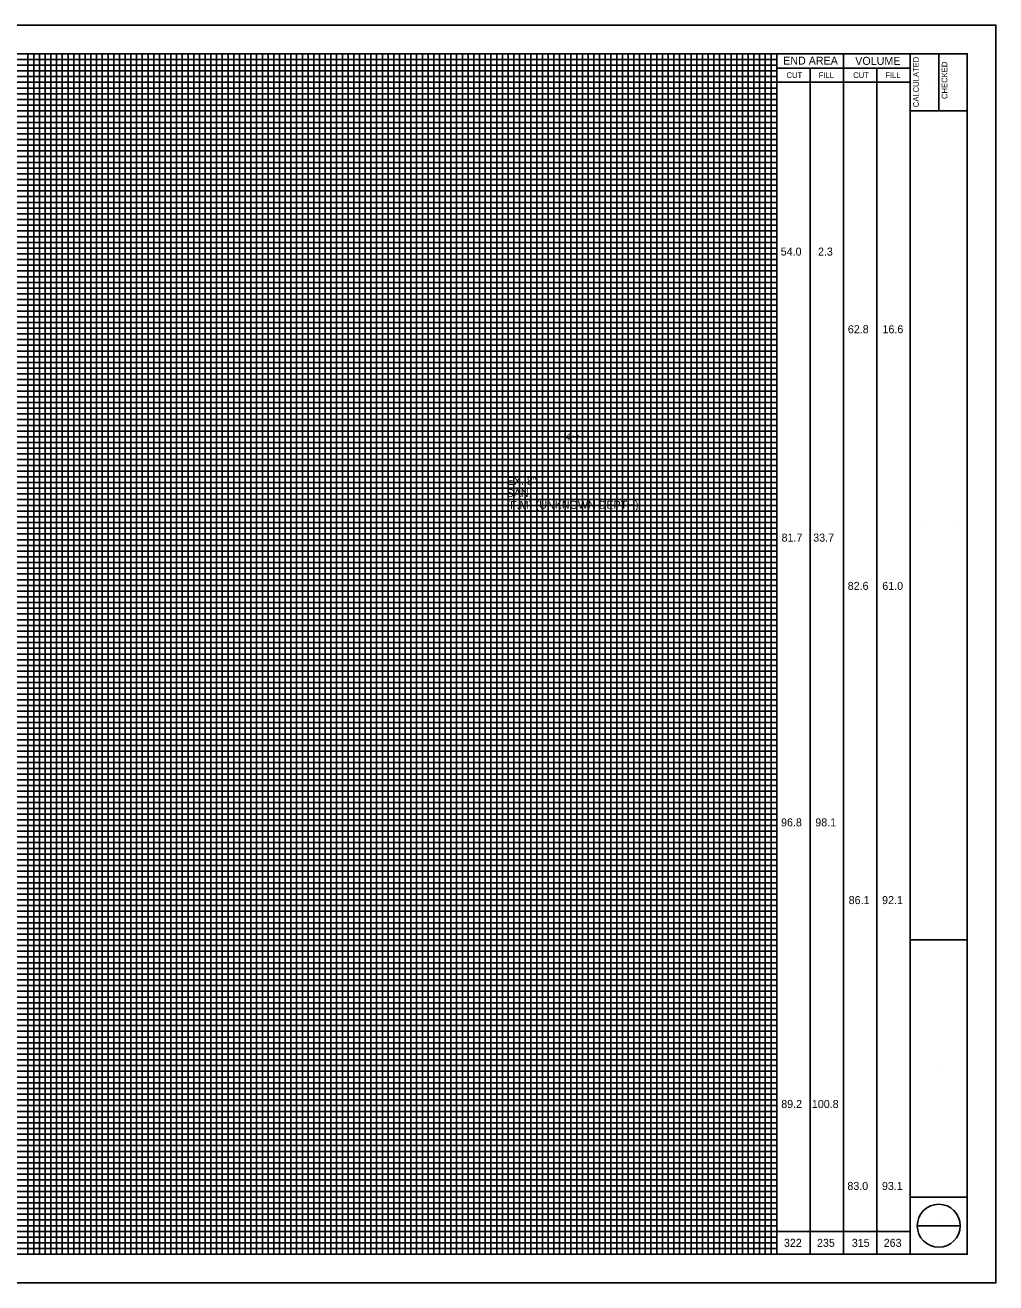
# Model space of a CAD drawing. Extents: x 2267521 to 2268201, y 654563 to 655003.
# Drawn here: x 2267861.3 to 2268201, y 654563.4 to 655003.4 of the extents above; entities that cross this region are included whole.
import ezdxf

# ---------------------------------------------------------------- set-up
doc = ezdxf.new("R2010")
doc.units = 0
for name, color, linetype in [('CL_X_Construction', 7, 'Continuous'), ('GK_Cells', 7, 'Continuous'), ('GK_Patterns', 7, 'Continuous'), ('MD_P_Surface_Finished_Grade', 7, 'Continuous'), ('PF_X_Ground_Line', 7, 'Continuous'), ('XS_X_Ground_Line', 7, 'Continuous')]:
    doc.layers.add(name, color=color, linetype=linetype)

msp = doc.modelspace()

# ---------------------------------------------------------------- linework, layer by layer
at = {"layer": 'CL_X_Construction'}
msp.add_lwpolyline([(2267520.96, 654563.36), (2268200.96, 654563.36), (2268200.96, 655003.36), (2267520.96, 655003.36)], close=True, dxfattribs=at)
at = {"layer": 'GK_Cells'}
for p, q in [((2267862.29, 654573.36), (2267862.29, 654993.36)), ((2267866.29, 654573.36), (2267866.29, 654993.36)), ((2267868.29, 654573.36), (2267868.29, 654993.36)), ((2267870.29, 654573.36), (2267870.29, 654993.36)), ((2267872.29, 654573.36), (2267872.29, 654993.36)), ((2267874.29, 654573.36), (2267874.29, 654993.36)), ((2267876.29, 654573.36), (2267876.29, 654993.36)), ((2267878.29, 654573.36), (2267878.29, 654993.36)), ((2267880.29, 654573.36), (2267880.29, 654993.36)), ((2267882.29, 654573.36), (2267882.29, 654993.36)), ((2267886.29, 654573.36), (2267886.29, 654993.36)), ((2267888.29, 654573.36), (2267888.29, 654993.36)), ((2267890.29, 654573.36), (2267890.29, 654993.36)), ((2267892.29, 654573.36), (2267892.29, 654993.36)), ((2267894.29, 654573.36), (2267894.29, 654993.36)), ((2267896.29, 654573.36), (2267896.29, 654993.36)), ((2267898.29, 654573.36), (2267898.29, 654993.36)), ((2267900.29, 654573.36), (2267900.29, 654993.36)), ((2267902.29, 654573.36), (2267902.29, 654993.36)), ((2267906.29, 654573.36), (2267906.29, 654993.36)), ((2267908.29, 654573.36), (2267908.29, 654993.36)), ((2267910.29, 654573.36), (2267910.29, 654993.36)), ((2267912.29, 654573.36), (2267912.29, 654993.36)), ((2267914.29, 654573.36), (2267914.29, 654993.36)), ((2267916.29, 654573.36), (2267916.29, 654993.36)), ((2267918.29, 654573.36), (2267918.29, 654993.36)), ((2267920.29, 654573.36), (2267920.29, 654993.36)), ((2267922.29, 654573.36), (2267922.29, 654993.36)), ((2267926.29, 654573.36), (2267926.29, 654993.36)), ((2267928.29, 654573.36), (2267928.29, 654993.36)), ((2267930.29, 654573.36), (2267930.29, 654993.36)), ((2267932.29, 654573.36), (2267932.29, 654993.36)), ((2267934.29, 654573.36), (2267934.29, 654993.36)), ((2267936.29, 654573.36), (2267936.29, 654993.36)), ((2267938.29, 654573.36), (2267938.29, 654993.36)), ((2267940.29, 654573.36), (2267940.29, 654993.36)), ((2267942.29, 654573.36), (2267942.29, 654993.36)), ((2267946.29, 654573.36), (2267946.29, 654993.36)), ((2267948.29, 654573.36), (2267948.29, 654993.36)), ((2267950.29, 654573.36), (2267950.29, 654993.36)), ((2267952.29, 654573.36), (2267952.29, 654993.36)), ((2267954.29, 654573.36), (2267954.29, 654993.36)), ((2267956.29, 654573.36), (2267956.29, 654993.36)), ((2267958.29, 654573.36), (2267958.29, 654993.36)), ((2267960.29, 654573.36), (2267960.29, 654993.36)), ((2267962.29, 654573.36), (2267962.29, 654993.36)), ((2267966.29, 654573.36), (2267966.29, 654993.36)), ((2267968.29, 654573.36), (2267968.29, 654993.36)), ((2267970.29, 654573.36), (2267970.29, 654993.36)), ((2267972.29, 654573.36), (2267972.29, 654993.36)), ((2267974.29, 654573.36), (2267974.29, 654993.36)), ((2267976.29, 654573.36), (2267976.29, 654993.36)), ((2267978.29, 654573.36), (2267978.29, 654993.36)), ((2267980.29, 654573.36), (2267980.29, 654993.36)), ((2267982.29, 654573.36), (2267982.29, 654993.36)), ((2267986.29, 654573.36), (2267986.29, 654993.36)), ((2267988.29, 654573.36), (2267988.29, 654993.36)), ((2267990.29, 654573.36), (2267990.29, 654993.36)), ((2267992.29, 654573.36), (2267992.29, 654993.36)), ((2267994.29, 654573.36), (2267994.29, 654993.36)), ((2267996.29, 654573.36), (2267996.29, 654993.36)), ((2267998.29, 654573.36), (2267998.29, 654993.36)), ((2268000.29, 654573.36), (2268000.29, 654993.36)), ((2268002.29, 654573.36), (2268002.29, 654993.36)), ((2268006.29, 654573.36), (2268006.29, 654993.36)), ((2268008.29, 654573.36), (2268008.29, 654993.36)), ((2268010.29, 654573.36), (2268010.29, 654993.36)), ((2268012.29, 654573.36), (2268012.29, 654993.36)), ((2268014.29, 654573.36), (2268014.29, 654993.36)), ((2268016.29, 654573.36), (2268016.29, 654993.36)), ((2268018.29, 654573.36), (2268018.29, 654993.36)), ((2268020.29, 654573.36), (2268020.29, 654993.36)), ((2268022.29, 654573.36), (2268022.29, 654993.36)), ((2268026.29, 654573.36), (2268026.29, 654993.36)), ((2268028.29, 654573.36), (2268028.29, 654993.36)), ((2268030.29, 654573.36), (2268030.29, 654993.36)), ((2268032.29, 654573.36), (2268032.29, 654993.36)), ((2268034.29, 654573.36), (2268034.29, 654993.36)), ((2268036.29, 654573.36), (2268036.29, 654993.36)), ((2268038.29, 654573.36), (2268038.29, 654993.36)), ((2268040.29, 654573.36), (2268040.29, 654993.36)), ((2268042.29, 654573.36), (2268042.29, 654993.36)), ((2268046.29, 654573.36), (2268046.29, 654993.36)), ((2268048.29, 654573.36), (2268048.29, 654993.36)), ((2268050.29, 654573.36), (2268050.29, 654993.36)), ((2268052.29, 654573.36), (2268052.29, 654993.36)), ((2268054.29, 654573.36), (2268054.29, 654993.36)), ((2268056.29, 654573.36), (2268056.29, 654993.36)), ((2268058.29, 654573.36), (2268058.29, 654993.36)), ((2268060.29, 654573.36), (2268060.29, 654993.36)), ((2268062.29, 654573.36), (2268062.29, 654993.36)), ((2268066.29, 654573.36), (2268066.29, 654993.36)), ((2268068.29, 654573.36), (2268068.29, 654993.36)), ((2268070.29, 654573.36), (2268070.29, 654993.36)), ((2268072.29, 654573.36), (2268072.29, 654993.36)), ((2268074.29, 654573.36), (2268074.29, 654993.36)), ((2268076.29, 654573.36), (2268076.29, 654993.36)), ((2268078.29, 654573.36), (2268078.29, 654993.36)), ((2268080.29, 654573.36), (2268080.29, 654993.36)), ((2268082.29, 654573.36), (2268082.29, 654993.36)), ((2268086.29, 654573.36), (2268086.29, 654993.36)), ((2268088.29, 654573.36), (2268088.29, 654993.36)), ((2268090.29, 654573.36), (2268090.29, 654993.36)), ((2268092.29, 654573.36), (2268092.29, 654993.36)), ((2268094.29, 654573.36), (2268094.29, 654993.36)), ((2268096.29, 654573.36), (2268096.29, 654993.36)), ((2268098.29, 654573.36), (2268098.29, 654993.36)), ((2268100.29, 654573.36), (2268100.29, 654993.36)), ((2268102.29, 654573.36), (2268102.29, 654993.36)), ((2268106.29, 654573.36), (2268106.29, 654993.36)), ((2268108.29, 654573.36), (2268108.29, 654993.36)), ((2268110.29, 654573.36), (2268110.29, 654993.36)), ((2268112.29, 654573.36), (2268112.29, 654993.36)), ((2268114.29, 654573.36), (2268114.29, 654993.36)), ((2268116.29, 654573.36), (2268116.29, 654993.36)), ((2268118.29, 654573.36), (2268118.29, 654993.36)), ((2268120.29, 654573.36), (2268120.29, 654993.36)), ((2268122.29, 654573.36), (2268122.29, 654993.36)), ((2267584.29, 654991.36), (2268124.29, 654991.36)), ((2267584.29, 654989.36), (2268124.29, 654989.36)), ((2267584.29, 654987.36), (2268124.29, 654987.36)), ((2267584.29, 654985.36), (2268124.29, 654985.36)), ((2267584.29, 654983.36), (2268124.29, 654983.36)), ((2267584.29, 654981.36), (2268124.29, 654981.36)), ((2267584.29, 654979.36), (2268124.29, 654979.36)), ((2267584.29, 654977.36), (2268124.29, 654977.36)), ((2267584.29, 654975.36), (2268124.29, 654975.36)), ((2267584.29, 654971.36), (2268124.29, 654971.36)), ((2267584.29, 654969.36), (2268124.29, 654969.36)), ((2267584.29, 654967.36), (2268124.29, 654967.36)), ((2267584.29, 654965.36), (2268124.29, 654965.36)), ((2267584.29, 654963.36), (2268124.29, 654963.36)), ((2267584.29, 654961.36), (2268124.29, 654961.36)), ((2267584.29, 654959.36), (2268124.29, 654959.36)), ((2267584.29, 654957.36), (2268124.29, 654957.36)), ((2267584.29, 654955.36), (2268124.29, 654955.36)), ((2267584.29, 654951.36), (2268124.29, 654951.36)), ((2267584.29, 654949.36), (2268124.29, 654949.36)), ((2267584.29, 654947.36), (2268124.29, 654947.36)), ((2267584.29, 654945.36), (2268124.29, 654945.36)), ((2267584.29, 654943.36), (2268124.29, 654943.36)), ((2267584.29, 654941.36), (2268124.29, 654941.36)), ((2267584.29, 654939.36), (2268124.29, 654939.36)), ((2267584.29, 654937.36), (2268124.29, 654937.36)), ((2267584.29, 654935.36), (2268124.29, 654935.36)), ((2267584.29, 654931.36), (2268124.29, 654931.36)), ((2267584.29, 654929.36), (2268124.29, 654929.36)), ((2267584.29, 654927.36), (2268124.29, 654927.36)), ((2267584.29, 654925.36), (2268124.29, 654925.36)), ((2267584.29, 654923.36), (2268124.29, 654923.36)), ((2267584.29, 654921.36), (2268124.29, 654921.36)), ((2267584.29, 654919.36), (2268124.29, 654919.36)), ((2267584.29, 654917.36), (2268124.29, 654917.36)), ((2267584.29, 654915.36), (2268124.29, 654915.36)), ((2267584.29, 654911.36), (2268124.29, 654911.36)), ((2267584.29, 654909.36), (2268124.29, 654909.36)), ((2267584.29, 654907.36), (2268124.29, 654907.36)), ((2267584.29, 654905.36), (2268124.29, 654905.36)), ((2267584.29, 654903.36), (2268124.29, 654903.36)), ((2267584.29, 654901.36), (2268124.29, 654901.36)), ((2267584.29, 654899.36), (2268124.29, 654899.36)), ((2267584.29, 654897.36), (2268124.29, 654897.36)), ((2267584.29, 654895.36), (2268124.29, 654895.36)), ((2267584.29, 654891.36), (2268124.29, 654891.36)), ((2267584.29, 654889.36), (2268124.29, 654889.36)), ((2267584.29, 654887.36), (2268124.29, 654887.36)), ((2267584.29, 654885.36), (2268124.29, 654885.36)), ((2267584.29, 654883.36), (2268124.29, 654883.36)), ((2267584.29, 654881.36), (2268124.29, 654881.36)), ((2267584.29, 654879.36), (2268124.29, 654879.36)), ((2267584.29, 654877.36), (2268124.29, 654877.36)), ((2267584.29, 654875.36), (2268124.29, 654875.36)), ((2267584.29, 654871.36), (2268124.29, 654871.36)), ((2267584.29, 654869.36), (2268124.29, 654869.36)), ((2267584.29, 654867.36), (2268124.29, 654867.36)), ((2267584.29, 654865.36), (2268124.29, 654865.36)), ((2267584.29, 654863.36), (2268124.29, 654863.36)), ((2267584.29, 654861.36), (2268124.29, 654861.36)), ((2267584.29, 654859.36), (2268124.29, 654859.36)), ((2267584.29, 654857.36), (2268124.29, 654857.36)), ((2267584.29, 654855.36), (2268124.29, 654855.36)), ((2267584.29, 654851.36), (2268124.29, 654851.36)), ((2267584.29, 654849.36), (2268124.29, 654849.36)), ((2267584.29, 654847.36), (2268124.29, 654847.36)), ((2267584.29, 654845.36), (2268124.29, 654845.36)), ((2267584.29, 654843.36), (2268124.29, 654843.36)), ((2267584.29, 654841.36), (2268124.29, 654841.36)), ((2267584.29, 654839.36), (2268124.29, 654839.36)), ((2267584.29, 654837.36), (2268124.29, 654837.36)), ((2267584.29, 654835.36), (2268124.29, 654835.36)), ((2267584.29, 654831.36), (2268124.29, 654831.36)), ((2267584.29, 654829.36), (2268124.29, 654829.36)), ((2267584.29, 654827.36), (2268124.29, 654827.36)), ((2267584.29, 654825.36), (2268124.29, 654825.36)), ((2267584.29, 654823.36), (2268124.29, 654823.36)), ((2267584.29, 654821.36), (2268124.29, 654821.36)), ((2267584.29, 654819.36), (2268124.29, 654819.36)), ((2267584.29, 654817.36), (2268124.29, 654817.36)), ((2267584.29, 654815.36), (2268124.29, 654815.36)), ((2267584.29, 654811.36), (2268124.29, 654811.36)), ((2267584.29, 654809.36), (2268124.29, 654809.36)), ((2267584.29, 654807.36), (2268124.29, 654807.36)), ((2267584.29, 654805.36), (2268124.29, 654805.36)), ((2267584.29, 654803.36), (2268124.29, 654803.36)), ((2267584.29, 654801.36), (2268124.29, 654801.36)), ((2267584.29, 654799.36), (2268124.29, 654799.36)), ((2267584.29, 654797.36), (2268124.29, 654797.36)), ((2267584.29, 654795.36), (2268124.29, 654795.36)), ((2267584.29, 654791.36), (2268124.29, 654791.36)), ((2267584.29, 654789.36), (2268124.29, 654789.36)), ((2267584.29, 654787.36), (2268124.29, 654787.36)), ((2267584.29, 654785.36), (2268124.29, 654785.36)), ((2267584.29, 654783.36), (2268124.29, 654783.36)), ((2267584.29, 654781.36), (2268124.29, 654781.36)), ((2267584.29, 654779.36), (2268124.29, 654779.36)), ((2267584.29, 654777.36), (2268124.29, 654777.36)), ((2267584.29, 654775.36), (2268124.29, 654775.36)), ((2267584.29, 654771.36), (2268124.29, 654771.36)), ((2267584.29, 654769.36), (2268124.29, 654769.36)), ((2267584.29, 654767.36), (2268124.29, 654767.36)), ((2267584.29, 654765.36), (2268124.29, 654765.36)), ((2267584.29, 654763.36), (2268124.29, 654763.36)), ((2267584.29, 654761.36), (2268124.29, 654761.36)), ((2267584.29, 654759.36), (2268124.29, 654759.36)), ((2267584.29, 654757.36), (2268124.29, 654757.36)), ((2267584.29, 654755.36), (2268124.29, 654755.36)), ((2267584.29, 654751.36), (2268124.29, 654751.36)), ((2267584.29, 654749.36), (2268124.29, 654749.36)), ((2267584.29, 654747.36), (2268124.29, 654747.36)), ((2267584.29, 654745.36), (2268124.29, 654745.36)), ((2267584.29, 654743.36), (2268124.29, 654743.36)), ((2267584.29, 654741.36), (2268124.29, 654741.36)), ((2267584.29, 654739.36), (2268124.29, 654739.36)), ((2267584.29, 654737.36), (2268124.29, 654737.36)), ((2267584.29, 654735.36), (2268124.29, 654735.36)), ((2267584.29, 654731.36), (2268124.29, 654731.36)), ((2267584.29, 654729.36), (2268124.29, 654729.36)), ((2267584.29, 654727.36), (2268124.29, 654727.36)), ((2267584.29, 654725.36), (2268124.29, 654725.36)), ((2267584.29, 654723.36), (2268124.29, 654723.36)), ((2267584.29, 654721.36), (2268124.29, 654721.36)), ((2267584.29, 654719.36), (2268124.29, 654719.36)), ((2267584.29, 654717.36), (2268124.29, 654717.36)), ((2267584.29, 654715.36), (2268124.29, 654715.36)), ((2267584.29, 654711.36), (2268124.29, 654711.36)), ((2267584.29, 654709.36), (2268124.29, 654709.36)), ((2267584.29, 654707.36), (2268124.29, 654707.36)), ((2267584.29, 654705.36), (2268124.29, 654705.36)), ((2267584.29, 654703.36), (2268124.29, 654703.36)), ((2267584.29, 654701.36), (2268124.29, 654701.36)), ((2267584.29, 654699.36), (2268124.29, 654699.36)), ((2267584.29, 654697.36), (2268124.29, 654697.36)), ((2267584.29, 654695.36), (2268124.29, 654695.36)), ((2267584.29, 654691.36), (2268124.29, 654691.36)), ((2267584.29, 654689.36), (2268124.29, 654689.36)), ((2267584.29, 654687.36), (2268124.29, 654687.36)), ((2267584.29, 654685.36), (2268124.29, 654685.36)), ((2267584.29, 654683.36), (2268124.29, 654683.36)), ((2267584.29, 654681.36), (2268124.29, 654681.36)), ((2267584.29, 654679.36), (2268124.29, 654679.36)), ((2267584.29, 654677.36), (2268124.29, 654677.36)), ((2267584.29, 654675.36), (2268124.29, 654675.36)), ((2267584.29, 654671.36), (2268124.29, 654671.36)), ((2267584.29, 654669.36), (2268124.29, 654669.36)), ((2267584.29, 654667.36), (2268124.29, 654667.36)), ((2267584.29, 654665.36), (2268124.29, 654665.36)), ((2267584.29, 654663.36), (2268124.29, 654663.36)), ((2267584.29, 654661.36), (2268124.29, 654661.36)), ((2267584.29, 654659.36), (2268124.29, 654659.36)), ((2267584.29, 654657.36), (2268124.29, 654657.36)), ((2267584.29, 654655.36), (2268124.29, 654655.36)), ((2267584.29, 654651.36), (2268124.29, 654651.36)), ((2267584.29, 654649.36), (2268124.29, 654649.36)), ((2267584.29, 654647.36), (2268124.29, 654647.36)), ((2267584.29, 654645.36), (2268124.29, 654645.36)), ((2267584.29, 654643.36), (2268124.29, 654643.36)), ((2267584.29, 654641.36), (2268124.29, 654641.36)), ((2267584.29, 654639.36), (2268124.29, 654639.36)), ((2267584.29, 654637.36), (2268124.29, 654637.36)), ((2267584.29, 654635.36), (2268124.29, 654635.36)), ((2267584.29, 654631.36), (2268124.29, 654631.36)), ((2267584.29, 654629.36), (2268124.29, 654629.36)), ((2267584.29, 654627.36), (2268124.29, 654627.36)), ((2267584.29, 654625.36), (2268124.29, 654625.36)), ((2267584.29, 654623.36), (2268124.29, 654623.36)), ((2267584.29, 654621.36), (2268124.29, 654621.36)), ((2267584.29, 654619.36), (2268124.29, 654619.36)), ((2267584.29, 654617.36), (2268124.29, 654617.36)), ((2267584.29, 654615.36), (2268124.29, 654615.36)), ((2267584.29, 654611.36), (2268124.29, 654611.36)), ((2267584.29, 654609.36), (2268124.29, 654609.36)), ((2267584.29, 654607.36), (2268124.29, 654607.36)), ((2267584.29, 654605.36), (2268124.29, 654605.36)), ((2267584.29, 654603.36), (2268124.29, 654603.36)), ((2267584.29, 654601.36), (2268124.29, 654601.36)), ((2267584.29, 654599.36), (2268124.29, 654599.36)), ((2267584.29, 654597.36), (2268124.29, 654597.36)), ((2267584.29, 654595.36), (2268124.29, 654595.36)), ((2267584.29, 654591.36), (2268124.29, 654591.36)), ((2267584.29, 654589.36), (2268124.29, 654589.36)), ((2267584.29, 654587.36), (2268124.29, 654587.36)), ((2267584.29, 654585.36), (2268124.29, 654585.36)), ((2267584.29, 654583.36), (2268124.29, 654583.36)), ((2267584.29, 654581.36), (2268124.29, 654581.36)), ((2267584.29, 654579.36), (2268124.29, 654579.36)), ((2267584.29, 654577.36), (2268124.29, 654577.36)), ((2267584.29, 654575.36), (2268124.29, 654575.36))]:
    msp.add_line(p, q, dxfattribs=at)
at = {"layer": 'GK_Patterns'}
for p, q in [((2268124.29, 654573.36), (2268124.29, 654993.36)), ((2268147.63, 654573.36), (2268147.63, 654993.36)), ((2268124.29, 654988.36), (2268170.96, 654988.36)), ((2268135.96, 654573.36), (2268135.96, 654988.36)), ((2268159.3, 654573.36), (2268159.3, 654988.36)), ((2268124.29, 654983.36), (2268170.96, 654983.36)), ((2268179.36, 654983.43), (2268179.36, 654983.43)), ((2268189.36, 654983.43), (2268189.36, 654983.43)), ((2268175.96, 654828.36), (2268175.96, 654828.36)), ((2268186, 654828.36), (2268186, 654828.36)), ((2268180.96, 654639.2), (2268180.96, 654639.2)), ((2268180.96, 654585.06), (2268180.96, 654585.06)), ((2268124.29, 654581.36), (2268170.96, 654581.36)), ((2268173.46, 654583.36), (2268188.46, 654583.36)), ((2268130.13, 654577.36), (2268130.13, 654577.36)), ((2268141.8, 654577.36), (2268141.8, 654577.36)), ((2268153.46, 654577.36), (2268153.46, 654577.36)), ((2268165.13, 654577.36), (2268165.13, 654577.36)), ((2268180.96, 654578.26), (2268180.96, 654578.26))]:
    msp.add_line(p, q, dxfattribs=at)
msp.add_circle((2268180.96, 654583.36), 7.5, dxfattribs=at)
at = {"layer": 'PF_X_Ground_Line'}
for p, q in [((2268170.96, 654573.36), (2268170.96, 654993.36)), ((2268180.96, 654993.36), (2268180.96, 654973.36)), ((2268170.96, 654973.36), (2268190.96, 654973.36)), ((2268170.96, 654683.36), (2268190.96, 654683.36)), ((2268170.96, 654593.36), (2268190.96, 654593.36))]:
    msp.add_line(p, q, dxfattribs=at)
msp.add_lwpolyline([(2267560.96, 654993.36), (2268190.96, 654993.36), (2268190.96, 654573.36), (2267560.96, 654573.36)], close=True, dxfattribs=at)
at = {"layer": 'XS_X_Ground_Line'}
for p, q in [((2267864.29, 654573.36), (2267864.29, 654993.36)), ((2267884.29, 654573.36), (2267884.29, 654993.36)), ((2267904.29, 654573.36), (2267904.29, 654993.36)), ((2267924.29, 654573.36), (2267924.29, 654993.36)), ((2267944.29, 654573.36), (2267944.29, 654993.36)), ((2267964.29, 654573.36), (2267964.29, 654993.36)), ((2267984.29, 654573.36), (2267984.29, 654993.36)), ((2268004.29, 654573.36), (2268004.29, 654993.36)), ((2268024.29, 654573.36), (2268024.29, 654993.36)), ((2268044.29, 654573.36), (2268044.29, 654993.36)), ((2268064.29, 654573.36), (2268064.29, 654993.36)), ((2268084.29, 654573.36), (2268084.29, 654993.36)), ((2268104.29, 654573.36), (2268104.29, 654993.36)), ((2267584.29, 654973.36), (2268124.29, 654973.36)), ((2267584.29, 654953.36), (2268124.29, 654953.36)), ((2267584.29, 654933.36), (2268124.29, 654933.36)), ((2267584.29, 654913.36), (2268124.29, 654913.36)), ((2267584.29, 654893.36), (2268124.29, 654893.36)), ((2267584.29, 654873.36), (2268124.29, 654873.36)), ((2267584.29, 654853.36), (2268124.29, 654853.36)), ((2267584.29, 654833.36), (2268124.29, 654833.36)), ((2267584.29, 654813.36), (2268124.29, 654813.36)), ((2267584.29, 654793.36), (2268124.29, 654793.36)), ((2267584.29, 654773.36), (2268124.29, 654773.36)), ((2267584.29, 654753.36), (2268124.29, 654753.36)), ((2267584.29, 654733.36), (2268124.29, 654733.36)), ((2267584.29, 654713.36), (2268124.29, 654713.36)), ((2267584.29, 654693.36), (2268124.29, 654693.36)), ((2267584.29, 654673.36), (2268124.29, 654673.36)), ((2267584.29, 654653.36), (2268124.29, 654653.36)), ((2267584.29, 654633.36), (2268124.29, 654633.36)), ((2267584.29, 654613.36), (2268124.29, 654613.36)), ((2267584.29, 654593.36), (2268124.29, 654593.36))]:
    msp.add_line(p, q, dxfattribs=at)

# ---------------------------------------------------------------- texts
at = {"layer": 'GK_Patterns'}
for s, height, p in [('END AREA', 2.8, (2268126.54, 654989.55)), ('VOLUME', 2.8, (2268151.76, 654989.46)), ('CUT', 2, (2268127.7, 654984.86)), ('FILL', 2, (2268138.97, 654984.86)), ('CUT', 2, (2268151.03, 654984.86)), ('FILL', 2, (2268162.3, 654984.86))]:
    msp.add_text(s, height=height, dxfattribs=at).set_placement(p)
for s, p in [('CALCULATED', (2268174.01, 654974.65)), ('CHECKED', (2268184.01, 654977.52))]:
    msp.add_text(s, height=2, rotation=90, dxfattribs=at).set_placement(p)
at = {"layer": 'MD_P_Surface_Finished_Grade'}
for s, p in [('54.0', (2268125.68, 654922.75)), ('2.3', (2268138.72, 654922.75)), ('62.8', (2268149.18, 654895.57)), ('16.6', (2268161.29, 654895.57)), ('EX. 8" ', (2268029.78, 654842.49)), ('SAN. ', (2268029.78, 654838.29)), ('(F.M)', (2268029.78, 654834.09)), ('(UNKNOWN DEPTH)', (2268039.95, 654834.15)), ('81.7', (2268125.98, 654822.68)), ('33.7', (2268137.06, 654822.68)), ('82.6', (2268149.12, 654805.79)), ('61.0', (2268161.22, 654805.79)), ('96.8', (2268125.8, 654723.05)), ('98.1', (2268137.79, 654723.05)), ('86.1', (2268149.46, 654695.86)), ('92.1', (2268161.15, 654695.86)), ('89.2', (2268125.87, 654624.53)), ('100.8', (2268136.58, 654624.53)), ('83.0', (2268149, 654595.87)), ('93.1', (2268161.1, 654595.87)), ('322', (2268126.8, 654575.96)), ('235', (2268138.37, 654575.96)), ('315', (2268150.56, 654575.96)), ('263', (2268161.72, 654575.96))]:
    msp.add_text(s, height=2.8, dxfattribs=at).set_placement(p)
msp.add_text('4:1', height=2.8, rotation=345.3911, dxfattribs=at).set_placement((2268050.06, 654858.34))

doc.saveas('drawing.dxf')
